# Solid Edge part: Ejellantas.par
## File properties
Author: there
Template: iso metric part.par
Last saved by: there
Revision: 2
Application: Solid Edge
Precisión: 0.990
Username: there
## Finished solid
Body 1: solid body, 3 faces, 2 edges, 0 vertices.
  Faces by surface: plane 2, cylinder 1
  Edges by curve: circle 2
Bounding box of the edges (mm): 6.400 x 170.000 x 6.400, from (-3.2, 0, -3.2) to (3.2, 170, 3.2).
Cylindrical faces by radius (mm): R3.2 x1
Planar faces by outward normal: +y 1, -y 1
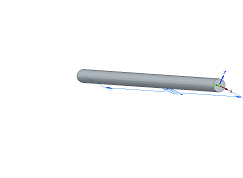
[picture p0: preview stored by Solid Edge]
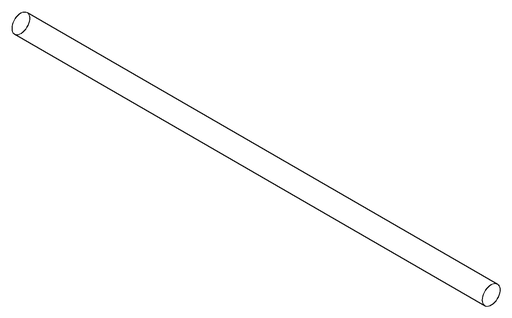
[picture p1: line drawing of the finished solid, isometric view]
